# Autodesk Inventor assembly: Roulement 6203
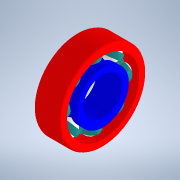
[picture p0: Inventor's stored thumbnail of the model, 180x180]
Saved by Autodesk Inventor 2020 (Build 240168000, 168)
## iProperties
Created: 2003-06
Part Number: Roulement 6203
Document SubType Name: Assembly
Designer: Bruno
Author: Bruno
Sending System: SolidWorks 2011
Last Author: Professeur
Last Saved: 2014-11-10
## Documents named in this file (5)
- D:\Téléchargements-2016-17\scoot_elec\pièces à assembler\ROULEMENT 6203\Roulement 6203.iam
- D:\Téléchargements-2016-17\scoot_elec\pièces à assembler\ROULEMENT 6203\Bague intérieure 6203.ipt
- D:\Téléchargements-2016-17\scoot_elec\pièces à assembler\ROULEMENT 6203\Cage 6203.ipt
- D:\Téléchargements-2016-17\scoot_elec\pièces à assembler\ROULEMENT 6203\Billes 6203.ipt
- D:\Téléchargements-2016-17\scoot_elec\pièces à assembler\ROULEMENT 6203\Bague extérieure 6203.ipt
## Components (11 placed, 4 different names)
1. Bague intérieure 6203:1
2. Cage 6203:1
3. Billes 6203:1
4. Billes 6203:2
5. Billes 6203:3
6. Billes 6203:4
7. Billes 6203:5
8. Billes 6203:6
9. Billes 6203:7
10. Billes 6203:8
11. Bague extérieure 6203:1
